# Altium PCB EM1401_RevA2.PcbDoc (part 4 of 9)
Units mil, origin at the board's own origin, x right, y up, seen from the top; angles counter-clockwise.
Board outline 7800 x 5300 mil, 6 copper layers (Top Layer, MidLayer1, MidLayer2, MidLayer3, MidLayer4, Bottom Layer), stack 16.8 mil thick; 751 components, 531 nets, 2554 pads, 1388 vias.
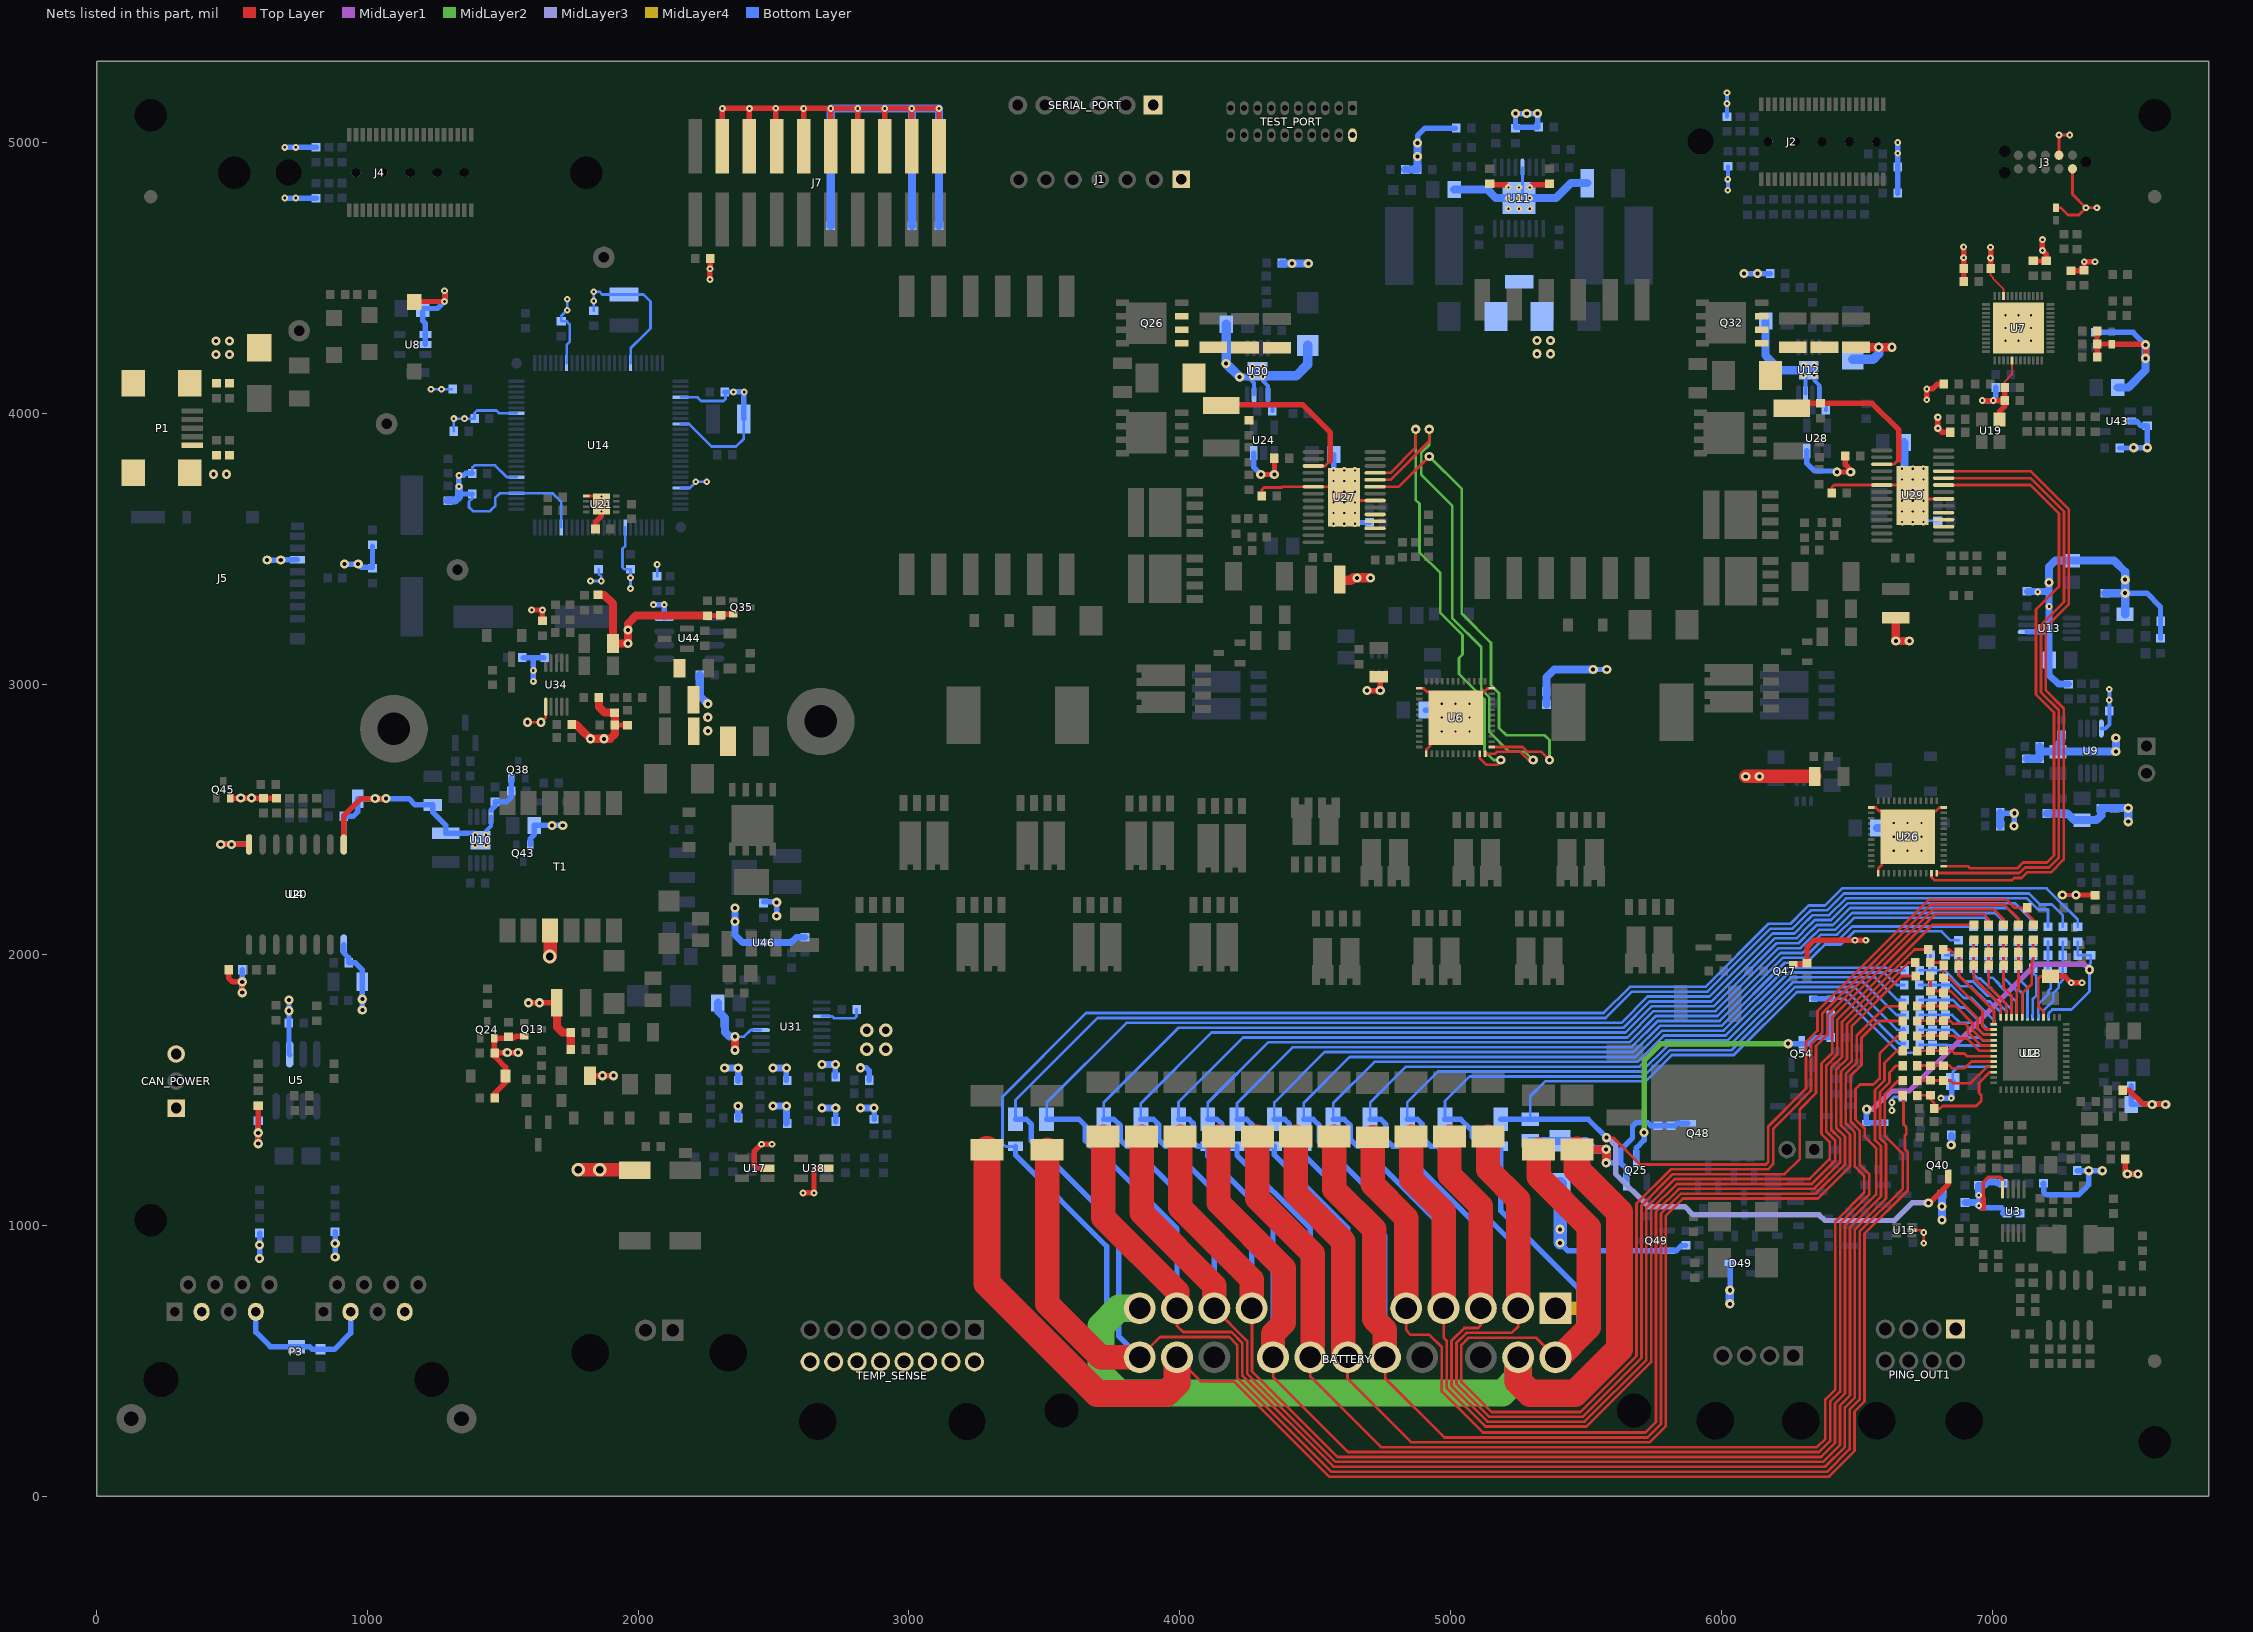
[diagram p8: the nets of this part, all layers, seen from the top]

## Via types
v1: diameter 25, hole 10, Top Layer to Bottom Layer, tented both sides, 275 vias
v2: diameter 16, hole 8, Top Layer to Bottom Layer, tented both sides, 240 vias
v3: diameter 34, hole 15, Top Layer to Bottom Layer, tented both sides, 158 vias
v4: diameter 34, hole 15, Top Layer to Bottom Layer, 154 vias
v5: diameter 34, hole 15, Top Layer to Bottom Layer, tented top, 95 vias
v6: diameter 34, hole 15, Top Layer to Bottom Layer, tented bottom, 89 vias
v7: diameter 25, hole 10, Top Layer to Bottom Layer, tented bottom, 75 vias
v8: diameter 25, hole 10, Top Layer to Bottom Layer, 62 vias
v9: diameter 28, hole 8, Top Layer to Bottom Layer, tented both sides, 60 vias
v10: diameter 24, hole 8, Top Layer to Bottom Layer, 53 vias
v11: diameter 25, hole 10, Top Layer to Bottom Layer, tented top, 28 vias
v12: diameter 50, hole 28, Top Layer to Bottom Layer, 28 vias
v13: diameter 25, hole 8, Top Layer to Bottom Layer, tented both sides, 18 vias
v14: diameter 50, hole 28, Top Layer to Bottom Layer, tented top, 12 vias
v15: diameter 25, hole 8, Top Layer to Bottom Layer, tented top, 9 vias
v16: diameter 20, hole 8, Top Layer to Bottom Layer, tented both sides, 9 vias
v17: diameter 24, hole 8, Top Layer to Bottom Layer, tented bottom, 4 vias
v18: diameter 24, hole 8, Top Layer to Bottom Layer, tented top, 4 vias
v19: diameter 28, hole 10, Top Layer to Bottom Layer, tented both sides, 3 vias
v20: diameter 35, hole 14, Top Layer to Bottom Layer, 3 vias
v21: diameter 50, hole 28, Top Layer to Bottom Layer, tented both sides, 2 vias
v22: diameter 50, hole 28, Top Layer to Bottom Layer, tented bottom, 2 vias
v23: diameter 30, hole 14, Top Layer to Bottom Layer, tented top, 2 vias
v24: diameter 28, hole 10, Top Layer to Bottom Layer, 1 vias
v25: diameter 35, hole 14, Top Layer to Bottom Layer, tented both sides, 1 vias
v26: diameter 35, hole 14, Top Layer to Bottom Layer, tented top, 1 vias

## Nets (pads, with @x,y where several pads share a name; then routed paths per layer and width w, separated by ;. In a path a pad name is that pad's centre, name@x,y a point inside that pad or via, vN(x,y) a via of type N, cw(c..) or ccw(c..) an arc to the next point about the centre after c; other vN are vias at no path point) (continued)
BAT0: BATTERY.1 BATTERY.19 C1.1 C6.2 C15.1 C17.1 C18.1 C19.1 C20.1 C21.2 C22.2 C24.2 C25.2 C27.2 C28.2 C29.2 C30.2 C31.2 C32.2 C33.1 C34.1 C35.2 C36.2 C37.2 C38.1 C39.1 C40.1 C41.2 C42.2 C43.1 C44.1 C45.2 C47.2 C48.1 C50.1 C52.2 C54.1 C56.1 C60.2 C65.1 C66.1 C67.2 C68.1 C69.2 C72.2 C73.1 C80.1 C82.1 C83.1 C84.1 C85.1 C86.1 C87.1 C88.1 C89.1 C92.2 C93.2 C94.1 C95.1 C98.2 C99.1 C101.1 C102.1 C103.1 C104.1 C105.2 C106.2 C107.1 C111.1 C112.1 C115.1 C117.1 C118.1 C119.1 C120.1 C122.2 C123.2 C124.2 C128.1 C130.2 C132.2 C133.2 C134.2 C138.1 C140.2 C141.2 C142.2 C143.2 C144.2 C145.2 C146.2 C147.2 C148.2 C149.2 C150.2 C151.2 C155.2 C156.2 C157.1 C160.2 C161.2 C162.2 C166.1 C167.2 C168.1 C196.2 C197.2 C200.1 C201.1 C202.1 C203.1 C204.1 C207.1 C208.1 C209.1 C210.1 C214.1 C215.2 C216.2 C220.2 C222.2 C224.1 C225.2 C226.2 C227.1 C229.1 C230.1 C231.1 C233.2 C235.1 C236.2 C239.2 C240.2 C241.1 C242.1 C243.1 C244.1 D1.2 D4.2 D6.2 D8.2 D9.2 D17.1 D20.1 D39.2 D42.1 D49.3 D51.2 D62.2 D63.2 F15.2 F19.1 J1.1 J2.39 J2.40 J2.41 J2.42 J2.43 J3.2 J3.10 J4.39 J4.40 J4.41 J4.42 J4.43 J5.6 J7.4 J7.6 J7.8 J7.10 J7.12 J7.14 J7.16 J7.18 J7.20 NT3.2 NT4.2 NT6.2 P1.5 P1.6 P1.7 P1.8 P1.9 PING_OUT1.1 Q13.2 Q24.2 Q26.1 Q26.2 Q26.3 Q32.1 Q32.2 Q32.3 Q35.2 Q38.2 Q43.2 Q45.2 Q47.2 Q49.2 R15.1 R22.2 R36.2 R39.2 R46.2 R57.2 R61.2 R77.1 R78.1 R79.1 R82.2 R90.1 R91.1 R94.1 R98.2 R113.2 R130.1 R146.1 R147.1 R149.1 R153.1 R169.2 R172.2 R179.1 R185.2 R187.1 R190.2 R197.1 R199.2 R211.2 R215.2 R216.2 R219.1 R222.1 R223.2 R224.1 R228.1 R241.2 R242.2 R244.2 R250.1 R251.2 R255.2 R256.2 R257.2 R279.2 R303.2 R304.2 SERIAL_PORT.1 SW1.1 T1.9 TEMP_SENSE.9 TEMP_SENSE.10 TEMP_SENSE.11 TEMP_SENSE.12 TEMP_SENSE.13 TEMP_SENSE.14 TEMP_SENSE.15 TEMP_SENSE.16 TEST_PORT.2 U2.4 U3.5 U4.9 U4.16 U6.1 U6.13 U6.36 U6.49 U7.5 U7.34 U7.49 U8.1 U8.2 U9.4 U10.4 U10.9 U11.5 U11.17 U12.1 U12.3 U12.9 U13.2 U14.4 U14.9 U14.21 U14.33 U14.45 U14.54 U14.57 U14.69 U14.82 U14.94 U15.2 U17.2 U18.4 U19.2 U20.9 U20.16 U21.5 U21.9 U24.3 U26.1 U26.13 U26.36 U26.49 U27.3 U27.4 U27.5 U27.7 U27.17 U27.20 U27.29 U28.3 U29.3 U29.4 U29.5 U29.7 U29.17 U29.20 U29.29 U30.1 U30.3 U30.9 U31.3 U31.12 U34.6 U38.2 U43.2 U44.4 U46.2 | length 43999.7
  Top Layer w7: C203.1@6994.44,4534 6994.44,4510.56 7003,4502 7003,4498 7041.88,4459.12 U7.34@7041.88,4434.09 ; C201.1@7046.44,4095 7046.44,4116.44 7073.38,4143.38 U7.5@7073.38,4195.91
  Top Layer w10: v3(1591,2859) v3(1641,2859) 1658.83,2876.83 U34.6@1658.83,2916.32 ; U21.5@1808.88,3694.53 1834.47,3694.53 U21.9@1864,3665 ; v11(2265,4534) v11@2265.56,4534.56 ; BATTERY.19@3990,513.9 4078.9,425 4200,425 4552,73 6397.73,73 6492.23,167.49 6492.23,313.35 6529.19,350.31 6529.19,970.45 6688.5,1129.77 6688.5,1272.02 6677.5,1283.02 6677.5,1333.07 6683,1338.57 6683,1364.35 6672.92,1374.44 6672.92,1477.09 R15.1@6669.35,1480.65 ; C128.1@4302.86,3695 4302.86,3717.44 4311.42,3726 4376.42,3726 4379.33,3728.92 U27.20@4493.28,3728.92 4569.07,3728.92 U27.29@4607.45,3690.53 4620.25,3677.74 U27.7@4721.62,3677.74 ; U27.17@4493.28,3805.69 4537.11,3805.69 4556.42,3825 ; U6.1@4885.06,2984.51 4900.49,2984.51 4914,2971 U6.49@4927.42,2971 ; U6.13@4910.65,2742.39 4910.65,2758.23 4924.42,2772 U6.49@4924.42,2801 ; U6.49@5110.42,2971 5123.42,2971 5136.93,2984.51 U6.36@5152.77,2984.51 ; C138.1@6408.86,3708 6408.86,3727.44 6416.42,3735 6592.64,3735 U29.20@6592.7,3735.06 6668.49,3735.06 6697.03,3706.52 U29.29@6706.88,3696.68 6719.67,3683.88 U29.7@6821.05,3683.88 ; U26.1@6554.06,2544.27 6570.15,2544.27 6583.42,2531 U26.49@6597.42,2531 ; U26.13@6579.65,2302.14 6579.65,2319.23 6592.42,2332 U26.49@6592.42,2348 ; U29.17@6592.7,3811.84 6638.25,3811.84 6655.42,3829 ; U15.2@6703.5,983 6740,983 v1(6748,975) v1(6748,935) ; U26.49@6778.42,2526 6782.42,2530 6791.42,2530 6805.68,2544.27 U26.36@6821.77,2544.27 ; U2.4@7189.91,1769.78 7189.91,1790.51 7170.42,1810 7170.42,1890.54 7170.47,1890.6 7170.47,1912.06 7179.07,1920.65 C1.1@7215.41,1920.65 C1.1@7233.41,1920.65 ; R90.1@7236,4759.62 7253.38,4759.62 7281,4732 7320,4732 v1(7347,4759) ; J3.2@7247,4953 v1(7247,5028) v1(7287,5028) ; J3.10@7297,4903 7297,4809 v1(7347,4759) ; v1(7387,4759) v1(7347,4759)
  Top Layer w12: 6967.42,1102 6967.42,1160.42 6987,1180 7029,1180 7038.84,1170.16 U3.5@7038.84,1133.84
  Top Layer w15: v3(7259.42,2221) v3(7309.42,2221) v3@7316.42,2221
  Top Layer w20: v4(458.44,2408.04) v4(498.44,2408.04) U20.16@563,2408.04 ; Q45.2@493,2579 v5(532.44,2579) v5(572.44,2579) R223.2@617,2579 ; R223.2@617,2579.12 C107.1@665,2579.12 ; U20.9@913,2408.04 913,2514 976,2577 v4(1028.86,2577) v4(1068.86,2577) ; SW1.1@1173,4410.95 1175.05,4413 v8(1285,4413) v8(1285,4453) ; C106.2@1470.56,1472 1470.56,1489.56 1510.47,1529.47 D51.2@1510.47,1553 1510.47,1584.53 1470.56,1624.44 R215.2@1470.56,1638 1468.59,1639.97 Q24.2@1468.59,1692.01 1520.01,1692.01 1521,1693 1542,1693 1549,1700 1579.42,1700 Q13.2@1580.01,1699.41 ; R215.2@1470.56,1639 v5(1516.82,1639) v5(1556.82,1639) ; v3(1595.14,1823) v3(1635.14,1823) C162.2@1699.7,1823 ; v1(1606.5,3273.5) v1(1646.5,3273.5) C160.2@1646.5,3233.56 ; C102.1@1822.3,1554 v5(1868.56,1554) v5(1908.56,1554) ; C115.1@1842.44,3575 1842.44,3599.44 1864,3621 v17(1864,3637.44) U21.9@1864,3665 ; C168.1@1914.18,2848.88 C168.1@1914.06,2849 1959.88,2849 R219.1@1960,2848.88 ; C104.1@2256,3252.88 2256.56,3253.44 R244.2@2305,3253.44 2308.97,3257.41 Q35.2@2350.5,3257.41 ; v11(2265,4494) v11(2265,4534) ; v11@2265.56,4534.56 C33.1@2265.56,4572 ; J7.4@2311,4986 v8(2311,5126) v8(2411,5126) ; J7.6@2411,4986 v8(2411,5126) ; U17.2@2477.66,1212 2439.42,1212 2429.42,1222 2429.42,1275 v1(2455.42,1301) v1(2494.42,1301) ; J7.8@2508,4987 v8(2508,5127) ; v11(2609,1121) v11(2649,1121) 2649.42,1121.42 2649.42,1202 2659.42,1212 U38.2@2695.42,1212 ; J7.10@2611,4986 v8(2611,5126) ; J7.12@2711,4986 v8(2711,5126) ; J7.14@2811,4986 2811,5122 2807,5126 v8(2711,5126) ; v8(2811,5126) v8@2907,5126 ; J7.16@2911,4986 v8(2911,5126) 3006,5126 3010,5122 J7.18@3010,4986 ; v8(3010,5126) v8(3111,5126) J7.20@3111,4986 ; R179.1@4156.42,4031.74 4453.68,4031.74 4556.42,3929 4556.42,3825 ; v5(4299.42,3774) v5(4349.42,3774) 4349.86,3774.44 C230.1@4349.86,3834 ; v5(4691.42,2976) v5@4735.42,2976 ; v5(4740.42,2976) v5@4735.42,2976 ; C207.1@4740.42,3026.7 4740.42,2981 v5@4735.42,2976 ; C95.1@5145,4844.5 5203.5,4844.5 v10(5213.63,4834.37) ; v10(5292.37,4834.37) 5301.5,4843.5 C94.1@5366,4843.5 ; Q47.2@6265.91,1965.59 6312.89,1965.59 R169.2@6316.42,1969.12 6316.42,2027.42 6343,2054 v1(6494,2054) v1(6534,2054) ; R197.1@6266.42,4036.74 C235.1@6366.42,4036.74 6557.26,4036.74 6655.42,3938.58 6655.42,3829 ; v5(6427.84,3783.15) v5(6477.84,3783.15) ; C231.1@6457.86,3842 6457.86,3810.13 v5@6477.84,3790.15 ; v1(6759,4050) v11(6759,4090) 6780,4090 6798,4108 R82.2@6818.01,4108 ; v19(6800,3985) v19(6800,3945) 6815,3930 C101.1@6845.88,3930 ; v3@6814,1021 v3(6815.42,1021) ; v1@6894.32,4574.56 v1@6894.88,4574 ; C242.1@6894.88,4487 C241.1@6894.88,4535 v1@6894.88,4574 ; v1(6894.88,4614.56) v1(6894.88,4574.56) v1@6894.88,4574 ; v1(6964,4047) v1(7004,4047) C40.1@7046.88,4047 ; 6967.42,1064 6967.42,1102 ; v1@6993.88,4573.56 6994.44,4573 C203.1@6994.44,4534 ; v1(6994.44,4573.56) v1(6994.44,4613.56) ; U19.2@7027.5,3977.5 7027.5,4007.5 7046.88,4026.88 C40.1@7046.88,4047 ; C201.1@7046.44,4095 7046.44,4047.44 C40.1@7046.88,4047 ; C214.1@7152,4563.12 7152.56,4562.56 C204.1@7200,4562.56 7200,4587.47 v1(7186,4601.47) v1(7186,4641.47) ; C1.1@7233.41,1920.65 7268.35,1920.65 v1(7292,1897) v1(7332,1897) ; C224.1@7292,4527.12 7339.56,4527.12 C227.1@7340,4527.56 v1(7340,4560) v1(7380,4560) ; v3@7316.42,2221 R303.2@7380,2221 ; C202.1@7387.56,4304 7387.56,4256.56 C244.1@7388.12,4256 ; C243.1@7388.12,4208 C244.1@7388.12,4256 ; R57.2@7482.53,1500 7506.42,1500 7558.64,1447.77 v3(7591.2,1447.77) v3(7641.2,1447.77) v3@7642.2,1447.77 ; R279.2@7491.53,1246 7491.53,1198.8 v3(7499.34,1191) v3(7539.34,1191) ; v3(7567,4203) v3(7567,4253) 7565.24,4254.76 R91.1@7442,4254.76 7440.76,4256 C244.1@7388.12,4256 ; v8(2411,5126) 2507,5126 v8(2508,5127) ; v8(2508,5127) 2610,5127 v8(2611,5126) ; v8(2611,5126) v8(2711,5126)
  Top Layer w30: C162.2@1699.7,1823 1699.7,1734.3 1721,1713 C82.1@1750.88,1713 1750.88,1651.12 C83.1@1751,1651 ; C167.2@1754.06,2851 1771.07,2851 1792.81,2829.26 1792.81,2828.69 v4(1823.5,2798) v4(1873.5,2798) 1897,2798 1914.06,2815.06 C168.1@1914.06,2849 1914.06,2893.32 C166.1@1912.5,2894.88 1876.12,2894.88 1855,2916 R222.1@1855,2950 ; R228.1@1851.5,3329.56 1874.44,3329.56 1907.06,3296.94 1907.06,3212.56 1907.15,3212.47 C157.1@1907.15,3150 ; C157.1@1907.15,3148 C157.1@1907.15,3150 ; C104.1@2256,3252.88 1991.88,3252.88 1962,3223 v3(1962,3200) v3(1962,3150) C157.1@1907.15,3150 ; v5(2357.3,1648) v5(2357.3,1698) ; C134.2@6497.75,4244.01 v3(6581.42,4244) v5(6630,4244) v5@6631.42,4244 ; C216.2@6644.42,3244.85 6644.42,3159 v4(6644.57,3158.85) 6644.72,3159 v4(6694.42,3159)
  Top Layer w35: C215.2@4602.07,3383 4632.42,3383 4641.42,3392 v5(4654.42,3392) v5(4704.42,3392)
  Top Layer w50: v12(1674,1994) 1674.63,1994.63 T1.9@1674.63,2090.76 ; v12(1778,1206) v12(1858,1206) F19.1@1987,1206 ; v3(6090.42,2659) v3(6140.42,2659) C209.1@6345.27,2659
  Top Layer w100: F15.2@3287.96,1280.23 F15.2@3288.19,1280 3288.19,786.81 3695,380 3950,380 3990,420 BATTERY.19@3990,513.9
  MidLayer4 w50: BATTERY.1@5387.64,695 NT4.2@5500,695
  Bottom Layer w10: v7(1234.7,4089) v7(1273.7,4089) R61.2@1311.01,4089 ; C22.2@1318.73,3933.69 1318.73,3979.73 v7(1319.43,3980.43) v7(1358.43,3980.43) C44.1@1395.73,3980.43 1395.73,4000.73 1405.16,4010.16 1476.84,4010.16 1486.89,4000.11 U14.69@1550.85,4000.11 ; v7@1337.44,3770.56 v7(1338,3770) ; C43.1@1386.88,3773 C43.1@1386.88,3778 1386.88,3798.88 1396,3808 1471,3808 1515.11,3763.89 U14.57@1550.85,3763.89 ; C29.2@1387.44,3702 1387.44,3686.44 1375,3674 1375,3653 1389.5,3638.5 1452.56,3638.5 1472,3657.94 1472,3687 1489.83,3704.83 U14.54@1550.85,3704.83 1683.17,3704.83 1716.2,3671.8 U14.45@1716.2,3578.85 ; U14.82@1735.89,4185.15 1735.89,4252.89 1747,4264 1747,4328 1734.88,4340.12 C31.2@1716,4340.12 1716,4359 v1(1738,4381) v1(1738,4421) ; v1(1824,3381) v1(1864,3381) 1864,3397 1854,3407 C45.2@1854,3423.73 ; C48.1@1836,4379.12 v1(1836,4415) v1(1836,4449.09) 1856.91,4449.09 1866.91,4439.09 C41.2@1948,4439.09 2018.91,4439.09 2045.5,4412.5 2045.5,4313.5 2024.5,4292.5 2024.44,4292.5 1972.11,4240.17 U14.94@1972.11,4185.15 ; U14.33@1952.43,3578.85 1952.43,3510.14 1942.27,3499.98 1942.27,3430.73 1949.27,3423.73 C36.2@1972,3423.73 v1(1972,3393) v1(1972,3353) ; R36.2@2070,3399.12 v1(2070,3442) ; U14.21@2157.15,3724.52 2190.52,3724.52 v1(2213,3747) v1(2253,3747) ; U14.9@2157.15,3960.74 2188.26,3960.74 2271.5,3877.5 2361.5,3877.5 2390.17,3906.17 C47.2@2390.17,3979 ; U14.4@2157.15,4059.17 2218.83,4059.17 2232.85,4045.15 2315.15,4045.15 2322.27,4052.27 C30.2@2322.27,4078.85 ; v7@2351.85,4078.85 v7(2352,4079) ; v5@2364.3,1705 v5(2357.3,1698) 2391.5,1698 2415.71,1722.21 U31.12@2453.71,1722.21 ; U31.3@2678.12,1773.39 2716.27,1773.39 2723.33,1766.32 2799.74,1766.32 2806.53,1773.12 C149.2@2806.53,1799 ; D39.2@3393.42,1292.61 3356.81,1292.61 3345.42,1304 3345.42,1476 3654.42,1785 5565.62,1785 5662.62,1882 5941.62,1882 6174.62,2115 6255,2115 6304,2164 6304.29,2164 6322.79,2182.5 6382.79,2182.5 6446.17,2245.88 7201.73,2245.88 7316.41,2131.2 R130.1@7316.41,2103.77 ; v1(6630,1425) v1(6630,1455) 6630,1468 6637,1475 C69.2@6670.88,1475 ; 6724.25,3598.25 6728.88,3602.88 C197.2@6799.42,3602.88 ; C68.1@6854.42,1533 6854.42,1566.63 6874.49,1586.71 U18.4@7006.84,1586.71
  Bottom Layer w12: v10(5253,4795) 5265.8,4807.8 U11.5@5265.8,4908.19
  Bottom Layer w15: U10.9@1418,2427 1438,2447 1438,2457 1456.39,2475.39 U10.4@1456.39,2509.63 U10.4@1456.39,2510.66 ; U30.3@4274.62,4069.37 4274.62,4112.43 4267.73,4119.31 v10(4267.73,4135.31) U30.9@4287.42,4155 4307.42,4135 4307.42,4119 4325.8,4100.61 U30.1@4325.8,4069.37 4325.8,4040.61 4341.98,4024.44 C225.2@4341.98,4009 ; C112.1@6021,5096 v1(6021,5144) v1(6021,5184) ; v1(6024,4823.88) v1(6024,4863.88) C111.1@6024,4911.88 ; U12.3@6310.62,4073.37 6310.62,4146.2 U12.9@6323.42,4159 6343.42,4139 6343.42,4121 6361.8,4102.61 U12.1@6361.8,4073.37 6361.8,4045.61 6386.42,4021 C226.2@6386.42,4012 ; U9.4@7403.59,2836 7418,2836 7433.12,2851.12 C161.2@7433.12,2900 7433.12,2940.88 v7(7433,2941) 7433,2980.76 v7(7433.12,2980.88)
  Bottom Layer w20: v4(458.44,2408.04) v4(498.44,2408.04) U4.9@563,2408.04 ; v6(630,3458) v6(680,3458) 680.55,3458.55 J5.6@741.56,3458.55 ; v1(695.12,4794.88) v1(735.12,4794.88) C103.1@811,4794.88 ; v1(695.12,4982.12) v1(735.12,4982.12) C50.1@811,4982.12 ; U4.16@913,2408.04 913.12,2408.16 C80.1@913.12,2512 948,2512 964.3,2528.3 C15.1@964.3,2577 v4(1028.86,2577) v4(1068.86,2577) 1153,2577 1176.3,2553.7 C60.2@1242,2553.7 1242,2526 1289,2479 C67.2@1289,2449.3 1395.7,2449.3 U10.9@1418,2427 ; v4(916,3443) v4(966,3443) 978.01,3430.99 1019,3430.99 C25.2@1019,3510.01 ; U8.2@1214.24,4254 U8.1@1214.24,4291.4 1214.24,4331.76 1205,4341 C32.2@1205,4387 1259,4387 v8(1285,4413) v8(1285,4453) ; v7@1337.44,3770.56 1355.56,3770.56 1363,3778 C43.1@1386.88,3778 ; 1338,3696 1344,3702 C29.2@1387.44,3702 ; v7(1338,3730) v7(1338,3770) ; U10.4@1456.43,2534.43 1472,2550 R216.2@1472,2564.88 1513.88,2564.88 1532,2583 R250.1@1532,2605.5 1532,2651.42 Q38.2@1531.41,2652.01 ; C28.2@1576,3098 1613,3098 ; Q43.2@1601.59,2406.5 1601.59,2429.59 1617,2445 C65.1@1617,2478 v3(1681.56,2478) v3(1721.56,2478) ; v7(1613,3010) v7(1613,3050) 1613,3098 ; C27.2@1651.01,3098 1613,3098 ; v1(2056.48,3293.52) v1(2096.48,3293.52) U44.4@2096.48,3244 ; C30.2@2319.12,4078.85 2322.27,4078.85 v7@2351.85,4078.85 ; v7(2352,4079) v7(2392,4079) 2390.17,4077.17 C47.2@2390.17,3979 ; C239.2@2462.97,2196 2463.42,2195.56 2509.86,2195.56 v5(2511.42,2194) v5(2511.42,2144) ; C148.2@2547.42,1536 v6(2547.42,1582) ; v6(2728.42,1595.12) 2728.53,1595 C146.2@2728.53,1549 ; v3@2729.42,1441.12 v3@2729.53,1441 ; C143.2@2729.53,1384 v3@2729.53,1434.88 ; v6(2821.42,1583) 2842.42,1583 2853.53,1571.88 C142.2@2853.53,1537 ; C141.2@2871.42,1392.12 v3(2871.42,1435) ; D39.2@3393.42,1292.61 3393.42,1260.58 3730,924 3730,465 3795,400 3953,400 3990,437 BATTERY.19@3990,513.9 ; U24.3@4273.42,3853.51 4273.42,3800 v5(4299.42,3774) ; v10(4568.08,3788.96) 4568.42,3789.29 C220.2@4568.42,3848 ; v10(4646.82,3592.11) 4651.6,3596.88 C196.2@4701.42,3596.88 ; v6(4878.6,4998.6) 4878.6,5025.6 4906,5053 R153.1@5018.01,5053 ; C208.1@4905.92,2904 4995.49,2904 v13(5018.92,2927.43) ; v13(5070.1,2927.43) 5070.67,2928 C17.1@5102.36,2928 ; v4(5404.42,936.42) 5433.64,907.2 Q49.2@5799,907.2 5833.2,907.2 5852.88,926.88 R185.2@5869.56,926.88 ; v5(5527,3054) v5(5577,3054) ; v6@6032.4,762.4 D49.3@6032.4,862 ; v3(6083.42,4516) v3(6133.42,4516) R190.2@6180.3,4516 ; U28.3@6316.01,3861 6316.01,3815.4 6344.42,3787 6424.69,3787 v5@6427.84,3790.15 ; R39.2@6651.88,4813 R22.2@6651.88,4909 6652,4909.12 v1(6652,4960) 6652,4999.88 v1(6651.88,5000) ; v13(6739.1,2487.18) 6739.28,2487 C118.1@6772.86,2487 ; v1(6811.42,1471) v1(6849,1471) 6851.42,1471 6851.42,1530 C68.1@6854.42,1533 ; v1@6949.68,1111.56 v1@6951.12,1113 ; v1(6951.12,1112) v1@6951.12,1075.12 ; v1@6952,1076 v1@6951.12,1075.12 ; v1(6964,4047) v1(7004,4047) 7013.44,4056.44 R146.1@7013.44,4096 ; C119.1@7029.41,2524.98 7031.39,2523 v6(7082,2523) 7082,2477 v6(7081,2476) ; C6.2@7038.88,1046.12 C6.2@7055,1046.12 ; C236.2@7103,1046.12 C6.2@7055,1046.12 ; U13.2@7129.98,3192.97 7210.04,3192.97 ; R256.2@7187.42,1153.88 R256.2@7190.42,1156.88 7190.42,1124.58 7201,1114 7320,1114 7357,1151 v3(7357,1203) ; R257.2@7314.53,1203 v3(7357,1203) ; R149.1@7382,4299 7521,4299 v3(7567,4253) ; v3(7407,1203) v3(7357,1203) ; C39.1@7471.12,3872 7522,3872 v3(7523,3873) v3(7573,3873) C99.1@7573,3953.44 7550.31,3953.44 7532.75,3971 U43.2@7510.24,3971 ; v6(7491.64,3335.68) 7571.32,3335.68 7622.12,3284.88 7622.12,3232.12 7622,3232 C85.1@7622,3169.12 ; v3(7499.34,1191) v3(7539.34,1191) ; C72.2@7513.41,1447.65 C72.2@7513.53,1447.77 ; C73.1@7513.53,1516.65 C73.1@7513.53,1515.65 C72.2@7513.53,1447.77 ; v3(7641.2,1447.77) v3(7591.2,1447.77) C72.2@7513.53,1447.77 ; v1(6951.12,1074) v1@6951.12,1075.12 ; v1(6951.12,1074) 6950.56,1074.56 v1@6951.12,1075.12 ; v1(6951.12,1074) 6959.12,1066 7035.12,1066 C6.2@7055,1046.12 ; C38.1@5240,5056.99 5321.5,5056.99 v3(5321.5,5107) v3(5281.5,5107) v3(5240,5106.99) C38.1@5240,5056.99
  Bottom Layer w25: v3(2319.42,1582) v3(2369.42,1582) 2369.42,1536.12 C151.2@2369.53,1536 ; v5(2357.42,2173) v5(2357.42,2123) 2357.42,2074 2386.01,2045.4 U46.2@2415.93,2045.4 2564.82,2045.4 2584.42,2065 C240.2@2616.42,2065 ; C150.2@2369.42,1398 v6(2369.42,1442) ; v3(2497.42,1442) v3(2547.42,1442) 2547.42,1378.12 C147.2@2547.53,1378 ; v6(2497.42,1582) v6(2547.42,1582) ; v6(2678.42,1595.12) v6(2728.42,1595.12) ; v3(2679.42,1435) v3(2729.42,1435) ; v3(2821.42,1435) v3(2871.42,1435) ; v3(4221.42,4134) 4266.42,4134 v10(4267.73,4135.31) ; v3(6849,1298) 6849.88,1297.12 R46.2@6849.88,1335 ; R304.2@6900,1085.56 6939.56,1085.56 v1@6950.56,1074.56 ; v1@6949.68,1111.56 6949.42,1111.82 R199.2@6949.42,1149 6972,1149 6984,1161 7015,1161 7019.12,1156.88 R255.2@7040.42,1156.88 ; R94.1@7129.64,3342.12 7205.08,3342.12 7210.64,3336.57 ; 7210.04,3192.97 7210.64,3193.57 ; v6@7210.64,3391 v6(7210.64,3375.57) 7210.64,3336.57 ; C117.1@7282,3000.12 7244.88,3000.12 7210.64,3034.36 C52.2@7210.64,3088.57 7210.64,3193.57 ; 7210.64,3193.57 v7(7210.64,3286.57) 7210.64,3336.57
  Bottom Layer w30: R147.1@1297,3677.44 1324.44,3677.44 1338,3691 1338,3696 v7(1338,3730) ; C229.1@2227.44,3034 2227.44,2956.98 v25(2257.42,2927) ; C145.2@2295.42,1823 2295.42,1792 2320.3,1767.12 C144.2@2320.3,1748 2320.3,1715.12 2337.42,1698 v5(2357.3,1698) v5(2357.3,1648) ; R77.1@2711,4692.12 v8(2711,5126) v8(2811,5126) v8(2911,5126) v8(3010,5126) ; R78.1@3011,4692.12 3011,5125 v8(3010,5126) ; R79.1@3111,4692.12 v8(3111,5126) v8(3010,5126) ; R172.2@4376.53,4553.44 v6(4414.98,4553.44) v4(4474.98,4553.44) ; C89.1@4832.91,4901 C88.1@4877.88,4901 v6@4877.88,4947.88 ; v6@4878,4948 v6(4878.6,4948.6) v6(4878.6,4998.6) ; C92.2@5014,4826 5136,4826 5167,4795 v10(5213.63,4795) v10(5253,4795) v10(5292.37,4795) 5390,4795 5445,4850 C93.2@5504.91,4850 ; C19.1@5354.53,2924 5354.53,2971.88 C18.1@5354.42,2972 5354.42,3025.42 5383,3054 v5@5517,3054 ; v3(5369.4,4219.6) v3@5370,4219 ; v3(5369.4,4268.6) v3@5370,4268 ; v6(6031.4,711.4) v6(6031.4,761.4) v6@6032,762 ; C140.2@6163.42,4341 6163.42,4213.24 6204.42,4172.24 6204.42,4169 6214.42,4159 U12.9@6323.42,4159 ; C210.1@6574.85,2467.98 6644.98,2467.98 ; v10(6667.51,3755.73) 6676.42,3764.64 6676.42,3892 C222.2@6675.42,3893 ; v3(6815.42,1021) v3(6815.42,1071) R113.2@6815.42,1116 ; C120.1@7029.41,2476.98 C119.1@7029.41,2524.98 ; C86.1@7127,2724.12 R251.2@7175,2724.12 ; R251.2@7175,2726.12 7176.12,2727.24 7176.12,2748 ; C87.1@7176.12,2770 7176.12,2748 ; C20.1@7201.12,2522 7201.24,2521.88 C34.1@7260,2521.88 7279.12,2521.88 7303,2498 C37.2@7332,2498 7386,2498 7403,2515 R242.2@7403,2541.88 R241.2@7453,2541.88 v6(7503,2541.88) v6(7503,2491.88) ; v6@7210.64,3391 7210.64,3433.22 7233.42,3456 C56.1@7293.42,3456 7450.42,3456 7491.64,3414.78 v6(7491.64,3385.68) v6(7491.64,3335.68) ; C105.2@7257,2812.44 7257,2790 7241,2774 C35.2@7243,2751 ; R98.2@7416.64,3335.68 v6(7491.64,3335.68) ; v6(7457,2801) v6(7457,2751) C35.2@7243,2751 ; C98.2@7464,4096 7504,4096 7567,4159 v3(7567,4203) v3(7567,4253) ; C54.1@7491.64,3257.57 v6(7491.64,3335.68) ; 7176.12,2748 7179.12,2751 C35.2@7243,2751
  Bottom Layer w35: C130.2@4171.42,4329 v5(4171.42,4184) v3(4221.42,4134) ; U30.9@4287.42,4155 4295.42,4155 4312.42,4138 4430.42,4138 4472.42,4180 D17.1@4472.42,4250.52 ; D20.1@6485.42,4200.26 6561.68,4200.26 6581.42,4220 v3(6581.42,4244)
  Bottom Layer w50: v4(5404.42,936.42) v4(5404.42,986.42) D42.1@5404.42,1155.52
  other v3: 5319.4,4219.6 5319.4,4268.6
  other v4: 432,3775 480,3775 441,4217 491,4217 441,4267 491,4267
  other v7: 7168.64,3340.57
  other v10: 1398.32,2404.32 1437.69,2404.32 1398.32,2443.68 1437.69,2443.68 4568.08,3592.11 4607.45,3592.11 6667.51,3598.25 6706.88,3598.25 6746.25,3598.25 4568.08,3631.48 4607.45,3631.48 4646.82,3631.48 6667.51,3637.62 6706.88,3637.62 6746.25,3637.62 4568.08,3670.85 4607.45,3670.85 4646.82,3670.85 6667.51,3676.99 6706.88,3676.99 6746.25,3676.99 4568.08,3710.22 4607.45,3710.22 4646.82,3710.22 6667.51,3716.36 6706.88,3716.36 6746.25,3716.36 4568.08,3749.59 4607.45,3749.59 4646.82,3749.59 6706.88,3755.73 6746.25,3755.73 4607.45,3788.96 4646.82,3788.96 6667.51,3795.1 6706.88,3795.1 6746.25,3795.1 4307.1,4135.31 4267.73,4174.69 4307.1,4174.69 5213.63,4755.63 5253,4755.63 5292.37,4755.63 5253,4834.37
  other v12: 2844.42,1652 2914.42,1652 2844.42,1722 2914.42,1722
  other v13: 6636.73,2384.82 6687.92,2384.82 6739.1,2384.82 6636.73,2436 6687.92,2436 6739.1,2436 6636.73,2487.18 6687.92,2487.18 4967.73,2825.06 5018.92,2825.06 5070.1,2825.06 4967.73,2876.24 5018.92,2876.24 5070.1,2876.24 4967.73,2927.43
  other v16: 7049.76,4267.76 7097,4267.76 7144.24,4267.76 7049.76,4315 7097,4315 7144.24,4315 7049.76,4362.24 7097,4362.24 7144.24,4362.24
  other v17: 1844.32,3665 1883.68,3665 1864,3692.56
  other v18: 6303.73,4139.31 6343.1,4139.31 6303.73,4178.69 6343.1,4178.69
  other v20: 2257.42,2827
  other v26: 2257.42,2877
BAT1: BATTERY.20 D35.2 D39.1 F14.2 R14.1 R124.1 | length 10906.7
  Top Layer w10: BATTERY.20@3852.2,513.9 3927.31,589 4183,589 4212,560 4212,439.22 4560.22,91 6390.28,91 6474.23,174.95 6474.23,320.8 6511.19,357.76 6511.19,977.91 6670.5,1137.22 6670.5,1263.87 6604,1330.37 6604,1486.21 6653.45,1535.65 R14.1@6669.35,1535.65
  Top Layer w90: F14.2@3510.19,1280 3510.19,711.81 3708.1,513.9 BATTERY.20@3852.2,513.9
  Bottom Layer w10: D39.1@3393.42,1393 3393.42,1464 3696.42,1767 5573.07,1767 5670.07,1864 5949.07,1864 6182.07,2097 6262.46,2097 6311.46,2146 6311.75,2146 6330.25,2164.5 6390.25,2164.5 6452.75,2227 7135.76,2227 7176.88,2185.88 7220.54,2185.88 7261.41,2145 R124.1@7261.41,2103.77
  Bottom Layer w20: D39.1@3393.42,1393 3433.42,1393 3451.42,1375 3451.42,1314 3472.81,1292.61 D35.2@3508.42,1292.61 3508.42,1258.58 3775.15,991.85 3775.15,590.95 BATTERY.20@3852.2,513.9
BAT2: BATTERY.8 D32.2 D35.1 F13.2 R13.1 R123.1 | length 10269.1
  Top Layer w10: BATTERY.8@3990,695 3990,630 4013,607 4190.46,607 4231,566.46 4231,447.09 4568.09,110 6383.82,110 6456.23,182.41 6456.23,328.26 6493.19,365.22 6493.19,985.37 6608,1100.18 6608,1300.91 6586,1322.91 6586,1493.66 6621,1528.66 6621,1566 6645.65,1590.65 R13.1@6669.35,1590.65
  Top Layer w90: F13.2@3717.42,1329 3717.42,1029.58 3990.29,756.71 BATTERY.8@3990.29,695
  Bottom Layer w10: D35.1@3508.42,1393 3508.42,1454 3803.42,1749 5631.06,1749 5728.06,1846 5956.53,1846 6189.53,2079 6269.91,2079 6318.91,2128 6319.2,2128 6337.7,2146.5 6397.7,2146.5 6460.2,2209 7128.3,2209 7169.42,2167.88 7205.62,2167.88 7206.41,2167.09 R123.1@7206.41,2103.77
  Bottom Layer w20: D35.1@3508.42,1393 3627.42,1393 3651.42,1369 3651.42,1314 3672.81,1292.61 D32.2@3719.42,1292.61 3719.42,1259.58 3990,989 BATTERY.8@3990,695
BAT3: BATTERY.7 D29.2 D32.1 F12.2 R12.1 R122.1 | length 9736
  Top Layer w10: BATTERY.7@4127.8,695 4127.91,695 4249,573.91 4249,454.54 4575.54,128 6376.37,128 6438.23,189.86 6438.23,335.72 6475.19,372.68 6475.19,992.82 6590,1107.63 6590,1293.46 6567.66,1315.8 6567.66,1500.77 6603,1536.12 6603,1601 6647.65,1645.65 R12.1@6669.35,1645.65
  Top Layer w90: F12.2@3859.42,1329 3859.42,1047.58 4128.09,778.91 BATTERY.7@4128.09,695
  Bottom Layer w10: D32.1@3719.42,1393 3719.42,1455 3995.42,1731 5638.52,1731 5735.52,1828 5963.99,1828 6196.99,2061 6277.37,2061 6326.37,2110 6326.66,2110 6345.16,2128.5 6405.16,2128.5 6467.66,2191 7084.42,2191 7084.42,2190.41 7084.71,2190.71 7151.41,2124 R122.1@7151.41,2103.77
  Bottom Layer w20: D32.1@3719.42,1393 3757.42,1393 3780.42,1370 3780.42,1317 3804.81,1292.61 D29.2@3856.42,1292.61 3856.42,1258.58 4127.8,987.2 BATTERY.7@4127.8,695
BAT4: BATTERY.6 D29.1 D43.2 F11.2 R11.1 R120.1 | length 9556.5
  Top Layer w10: BATTERY.6@4267,695 4267,462 4583,146 6368.91,146 6420.23,197.32 6420.23,343.17 6457.19,380.13 6457.19,1000.28 6572,1115.09 6572,1286 6530,1328 6530,1358 6496,1392 6496,1504 6513,1521 6562.43,1521 6585,1543.57 6585,1635 6650.65,1700.65 R11.1@6669.35,1700.65
  Top Layer w90: F11.2@4001.42,1329 4001.42,1065.58 4265.88,801.12 BATTERY.6@4265.88,695
  Bottom Layer w10: D29.1@3856.42,1393 3856.42,1452 4117.42,1713 5645.97,1713 5742.97,1810 5971.44,1810 6204.44,2043 6284.82,2043 6333.82,2092 6334.11,2092 6352.61,2110.5 6412.61,2110.5 6475.11,2173 7055.42,2173 7096.41,2132 R120.1@7096.41,2103.77
  Bottom Layer w20: D29.1@3856.42,1393 3902.42,1393 3922.42,1373 3922.42,1318 3947.81,1292.61 D43.2@3995.42,1292.61 3995.42,1258.58 4265.59,988.41 BATTERY.6@4265.59,695
BAT5: BATTERY.17 D40.2 D43.1 F10.2 R10.1 R118.1 | length 9458.5
  Top Layer w10: BATTERY.17@4345,509 4345,441 4622,164 6361.46,164 6402.23,204.77 6402.23,350.63 6439.19,387.59 6439.19,1007.73 6546,1114.54 6546,1191 6511,1226 6511,1351 6478,1384 6478,1553.84 6518,1593.84 6518,1694 6579.65,1755.65 R10.1@6669.35,1755.65
  Top Layer w90: F10.2@4143.42,1329 4143.42,1083.58 4384.42,842.58 4384.42,641.42 4344.33,601.33 BATTERY.17@4344.33,513.9
  Bottom Layer w10: D43.1@3995.42,1393 3995.42,1456 4234.42,1695 5653.43,1695 5750.43,1792 5978.9,1792 6211.9,2025 6292.28,2025 6341.28,2074 6341.57,2074 6360.07,2092.5 6420.07,2092.5 6482.57,2155 7010.42,2155 7040.41,2125 R118.1@7040.41,2103.77
  Bottom Layer w20: D43.1@3995.42,1393 4034.42,1393 4049.42,1378 4049.42,1309 4065.81,1292.61 D40.2@4103.42,1292.61 4103.42,1256.58 4344.33,1015.67 BATTERY.17@4344.33,513.9
BAT6: BATTERY.16 D37.2 D40.1 F9.2 R9.1 R116.1 | length 9134.5
  Top Layer w10: BATTERY.16@4482.13,513.9 4482.13,442.87 4743,182 6354,182 6384.23,212.23 6384.23,358.08 6421.19,395.04 6421.19,1015.19 6528,1122 6528,1183.54 6493,1218.54 6493,1343.54 6460,1376.54 6460,1561.29 6500,1601.29 6500,1701.46 6609.2,1810.65 R9.1@6669.35,1810.65
  Top Layer w90: F9.2@4286.42,1329 4286.42,1100.58 4491,896 4491,522.48 BATTERY.16@4482.42,513.9
  Bottom Layer w10: D40.1@4103.42,1393 4103.42,1454 4326.42,1677 5660.89,1677 5757.89,1774 5986.35,1774 6219.35,2007 6299.73,2007 6348.73,2056 6349.03,2056 6367.53,2074.5 6427.53,2074.5 6490.03,2137 6973.42,2137 6986.41,2124 R116.1@6986.41,2103.77
  Bottom Layer w20: D40.1@4103.42,1393 4137.42,1393 4155.42,1375 4155.42,1313 4175.81,1292.61 D37.2@4211.42,1292.61 4211.42,1259.58 4482.13,988.87 BATTERY.16@4482.13,513.9
BAT7: BATTERY.15 D33.2 D37.1 F8.1 R8.1 R114.1 | length 8819.2
  Top Layer w10: BATTERY.15@4619.92,513.9 4619.92,436.08 4856,200 5735,200 5795,260 5795,1037 5858,1100 6356.37,1100 6475,1218.63 6475,1336.09 6442,1369.09 6442,1568.75 6482,1608.75 6482,1737.28 6666.38,1921.65 R8.1@6717.29,1921.65
  Top Layer w90: F8.1@4428.42,1329 4428.42,1118.58 4604,943 4604,526.59 BATTERY.15@4616.69,513.9
  Bottom Layer w10: D37.1@4211.42,1393 4211.42,1452 4418.42,1659 5668.34,1659 5765.34,1756 5993.81,1756 6226.81,1989 6307.19,1989 6356.19,2038 6356.48,2038 6374.98,2056.5 6434.98,2056.5 6483.48,2105 6930.19,2105 R114.1@6931.41,2103.77
  Bottom Layer w20: D37.1@4211.42,1393 4247.42,1393 4270.42,1370 4270.42,1306 4283.81,1292.61 D33.2@4349.42,1292.61 4349.42,1261.58 4619.92,991.08 BATTERY.15@4619.92,513.9
BAT8: BATTERY.14 D30.2 D33.1 F7.2 R7.1 R112.1 | length 8483.2
  Top Layer w10: BATTERY.14@4759,513.9 4759,436 4977,218 5727.54,218 5777,267.46 5777,1044.46 5850.54,1118 6348.91,1118 6457,1226.09 6457,1328.63 6424,1361.63 6424,1576.21 6464,1616.21 6464,1744.73 6690.92,1971.65 R7.1@6716.85,1971.65
  Top Layer w90: F7.2@4570.42,1329 4570.42,1133.58 4717.92,986.08 4717.92,655.07 4757.72,615.27 BATTERY.14@4757.72,513.9
  Bottom Layer w10: D33.1@4349.42,1393 4349.42,1455 4535.42,1641 5675.8,1641 5772.8,1738 6001.27,1738 6234.27,1971 6314.65,1971 6363.65,2020 6363.94,2020 6382.44,2038.5 6442.44,2038.5 6490.94,2087 6814,2087 6847.23,2053.77 R112.1@6876.41,2053.77
  Bottom Layer w20: D33.1@4349.42,1393 4387.42,1393 4405.42,1375 4405.42,1310 4422.81,1292.61 D30.2@4458.42,1292.61 4458.42,1261.58 4757.72,962.28 BATTERY.14@4757.72,513.9
BAT9: BATTERY.5 D30.1 D41.2 F6.1 R6.1 R111.1 | length 7851.7
  Top Layer w10: BATTERY.5@4836.75,695 4836.75,613.25 4853,597 4922,597 4967.99,551.01 4967.99,387.53 5119.52,236 5720.09,236 5759,274.91 5759,1051.91 5843.09,1136 6341.46,1136 6439,1233.54 6439,1321.18 6406,1354.18 6406,1583.66 6446,1623.66 6446,1752.54 6713.11,2019.65 R6.1@6763.85,2019.65
  Top Layer w90: F6.1@4712.42,1327 4712.42,1152.58 4836.75,1028.25 BATTERY.5@4836.75,695
  Bottom Layer w10: D30.1@4458.42,1393 4458.42,1454 4627.42,1623 5683.25,1623 5780.25,1720 6008.72,1720 6241.72,1953 6607.87,1953 6618.22,1942.65 R111.1@6677.74,1942.65
  Bottom Layer w20: D30.1@4458.42,1393 4492.42,1393 4515.42,1370 4515.42,1309 4531.81,1292.61 D41.2@4566.42,1292.61 4566.42,1264.58 4836.46,994.54 BATTERY.5@4836.46,695
BAT10: BATTERY.4 D38.2 D41.1 F5.2 R5.1 R110.1 | length 7719.1
  Top Layer w10: BATTERY.4@4974.54,695 4974.54,586.46 4985.99,575.01 4985.99,400.64 5128.63,258 5502.46,258 5741,496.54 5741,1059.37 5835.63,1154 6334,1154 6420.75,1240.75 6420.75,1313.97 6388,1346.72 6388,1591.12 6428,1631.12 6428,1760 6779.21,2111.21 R5.1@6932.91,2111.21
  Top Layer w90: F5.2@4854.42,1329 4854.42,1171.58 4974.54,1051.46 BATTERY.4@4974.54,695
  Bottom Layer w10: D41.1@4566.42,1393 4566.42,1452 4719.42,1605 5690.71,1605 5787.71,1702 6016.18,1702 6249.18,1935 6600.42,1935 6646.76,1888.65 R110.1@6675.74,1888.65
  Bottom Layer w20: D41.1@4566.42,1393 4607.42,1393 4630.42,1370 4630.42,1319 4656.81,1292.61 D38.2@4703.42,1292.61 4703.42,1262.58 4974.25,991.75 BATTERY.4@4974.25,695
BAT11: BATTERY.3 D36.2 D38.1 F4.2 R4.1 R109.1 | length 7720.8
  Top Layer w10: BATTERY.3@5111,691 5111,631 5102,622 5051,622 5003.99,574.99 5003.99,408.1 5136.09,276 5495.01,276 5723,503.99 5723,1066.82 5828.18,1172 6326.14,1172 6400,1245.86 6400,1309.27 6370,1339.27 6370,1598.57 6410,1638.57 6410,1770.63 6789.37,2150 6969.42,2150 6986.91,2132.5 R4.1@6986.91,2111.21
  Top Layer w90: F4.2@4996.42,1329 4996.42,1188.58 5112.34,1072.66 BATTERY.3@5112.34,695
  Bottom Layer w10: D38.1@4703.42,1393 4703.42,1454 4836.42,1587 5698.16,1587 5795.16,1684 6023.63,1684 6256.63,1917 6567.42,1917 6650.76,1833.65 R109.1@6677.74,1833.65
  Bottom Layer w20: D38.1@4703.42,1393 4742.42,1393 4760.42,1375 4760.42,1319 4786.81,1292.61 D36.2@4840.42,1292.61 4840.42,1256.58 5112.05,984.95 BATTERY.3@5112.05,695
BAT12: BATTERY.2 D34.2 D36.1 F3.2 R3.1 R108.1 | length 7669.9
  Top Layer w10: BATTERY.2@5250.13,695 5250.13,628.13 5226,604 5058.46,604 5021.99,567.54 5021.99,415.55 5143.54,294 5487.55,294 5705,511.45 5705,1074.28 5820.72,1190 6234,1190 6290,1246 6290,1430 6350,1490 6350,1664.09 6391,1705.09 6391,1706 6392,1707 6392,1778.09 6781.91,2168 7006.42,2168 7042.91,2131.5 R3.1@7042.91,2111.21
  Top Layer w90: F3.2@5138.42,1329 5138.42,1207.58 5250.13,1095.87 BATTERY.2@5250.13,695
  Bottom Layer w10: D36.1@4840.42,1393 4840.42,1456 4953.42,1569 5705.62,1569 5802.62,1666 6031.09,1666 6264.09,1899 6525.42,1899 6646.76,1777.65 R108.1@6677.74,1777.65
  Bottom Layer w20: D36.1@4840.42,1393 4877.42,1393 4895.42,1375 4895.42,1326 4928.81,1292.61 D34.2@4979.42,1292.61 4979.42,1186.99 5249.84,916.56 BATTERY.2@5249.84,695
BAT13: BATTERY.10 D31.2 D34.1 F2.2 R2.1 R107.1 | length 8113.7
  Top Layer w10: BATTERY.10@5394.27,507.27 BATTERY.10@5387.64,513.9 5315.58,585.95 5233.5,585.95 5233.46,586 5065.91,586 5039.99,560.08 5039.99,423.01 5151,312 5480.1,312 5687,518.9 5687,1081.73 5813.27,1208 6171.76,1208 6191.42,1227.66 6191.42,1357.42 6287,1453 6287,1454.54 6331,1498.54 6331,1670.54 6373,1712.54 6373,1784.54 6774.46,2186 7044.42,2186 7096.91,2133.5 R2.1@7096.91,2111.21
  Top Layer w90: F2.2@5325.42,1281 5325.42,1180.58 5511,995 5511,624 BATTERY.10@5394.27,507.27
  Bottom Layer w10: D34.1@4979.42,1393 4979.42,1460 5070.42,1551 5713.08,1551 5810.08,1648 6038.54,1648 6271.54,1881 6491.42,1881 6648.76,1723.65 R107.1@6677.29,1723.65 R107.1@6671.95,1729
  Bottom Layer w20: D34.1@4979.42,1393 5037.42,1393 5080.42,1350 5080.42,1328 5115.81,1292.61 D31.2@5185.42,1292.61 5185.42,1055.58 5475,766 5475,601.26 BATTERY.10@5387.64,513.9
BAT14: BATTERY.9 BATTERY.11 D42.2 F1.2 Q25.2 Q48.2 R89.2 R129.1 R183.2 | length 4372.2
  Top Layer w30: F1.2@5467.42,1281 5468.42,1281 v3@5575,1281 ; v3(5575,1232) v3@5575,1281 ; v3@5575,1281 5576,1281 v3(5575,1282) v3@5575,1281
  Top Layer w50: F1.2@5467.42,1280 F1.2@5468.42,1281
  Top Layer w100: BATTERY.11@5249.84,513.9 5249.84,425.16 5294,381 5460,381 5624,545 5624,1050 5467.42,1206.58 F1.2@5467.42,1280
  MidLayer2 w100: BATTERY.9@3852.2,695 3775,695 3709,629 3709,450 3777,382 5192,382 5249.84,439.84 BATTERY.11@5249.84,513.9
  Bottom Layer w20: v3(5575,1232) 5628,1232 ; Q25.2@5649.2,1165 5649.2,1210.8 5628,1232 ; Q48.2@5877,1378.8 5838.8,1378.8 5829,1369 R183.2@5814,1369 R89.2@5766,1369 5740,1369 5728,1381 5686,1381 5672,1367 5672,1324 5628,1280 5628,1232
  Bottom Layer w30: R129.1@5294.42,1313 D42.2@5404.42,1313 5500,1313 5531,1282 v3(5575,1282) v3(5575,1232)
BAT14S_: D31.1 Q40.2 R1.1 R106.1 R126.2 R129.2 | length 5963
  Top Layer w10: v3(5576,1325) 5601,1325 5700,1226 6164.3,1226 6173.42,1235.12 6173.42,1366.42 6313,1506 6313,1678 6355,1720 6355,1792 6767,2204 7053.42,2204 7083.42,2173.99 7126.42,2173.99 7126.42,2154.58 7152.91,2128.09 R1.1@7152.91,2111.21
  Top Layer w20: v3@6769,1084 6768.42,1084 6838.82,1154.4 Q40.2@6838.82,1181.32 ; R1.1@7152.91,2111.21 R1.1@7153.13,2111
  MidLayer3 w20: v3(5576,1325) 5581.5,1325 5610,1296.5 5610,1191 5731,1070 5865.5,1070 5895.5,1040 6361.5,1040 6382.5,1019 6639.92,1019 6704.92,1084 v3(6764.42,1084) ; v3@6766,1081 v3@6769,1084
  Bottom Layer w10: R129.2@5294.42,1393 5294.42,1478 5349.42,1533 5720.53,1533 5817.53,1630 6046,1630 6279,1863 6465.42,1863 6655.42,1673 R106.1@6677.42,1673
  Bottom Layer w20: D31.1@5185.42,1393 R129.2@5294.42,1393 5508,1393 v3(5576,1325)
C0: C189.2 C192.1 D55.2 D56.2 R130.2 U18.22 | length 1611.2
  MidLayer1 w20: v3(6537,1430) 6560.52,1430 6627.81,1497.29 6694.1,1497.29 7162.81,1966 7339,1966 v3(7360,1945)
  Bottom Layer w10: U18.22@7209.59,1769.78 7209.59,1785.21 7222.38,1798 7292.82,1798 7359.42,1864.6 7359.42,1964.42 7364.41,1969.41 C192.1@7364.41,1998.65 C189.2@7316.53,1998.65 R130.2@7316.53,2048.54
  Bottom Layer w20: v3(6537,1430) 6541.42,1430 6541.42,1417.42 6535,1411 6535,1379.53 D56.2@6535.42,1379.12 6536.3,1380 D55.2@6602.42,1380
C1: C186.2 C189.1 R124.2 U18.21 | length 308.6
  Bottom Layer w10: U18.21@7189.91,1769.78 7189.91,1794.14 7226.42,1830.65 7226.42,1860 7246.42,1880 7246.42,1893.08 7261.53,1908.2 C186.2@7261.53,1950.65 7261.53,1998.54 C189.1@7261.41,1998.65 R124.2@7261.41,2048.65
C2: C184.2 C186.1 R123.2 U18.20 | length 302.2
  Bottom Layer w10: U18.20@7170.22,1769.78 7170.22,1816.89 7208.42,1855.08 7208.42,1868 7216.42,1876 7216.42,1919 7206.41,1929 C186.1@7206.41,1950.65 C184.2@7206.53,1998.65 7206.53,2048.54 R123.2@7206.41,2048.65
C3: C108.2 C184.1 R122.2 U18.19 | length 290.6
  Bottom Layer w10: U18.19@7150.54,1769.78 7150.54,1837.58 7163.42,1850.46 7163.42,1921 7151.53,1932.89 C108.2@7151.53,1950.65 ; C108.2@7150.54,1949.66 C108.2@7151.53,1950.65 ; R122.2@7151.41,2048.65 C184.1@7151.41,1998.65 7151.53,1998.54 C108.2@7151.53,1950.65
C4: C108.1 C193.2 R120.2 U18.18 | length 293.2
  Bottom Layer w10: R120.2@7096.41,2048.65 7096.53,2048.54 C193.2@7096.53,1998.65 7096.53,1950.77 C108.1@7096.41,1950.65 7096.41,1914.66 7130.85,1880.22 U18.18@7130.85,1769.78
C5: C190.2 C193.1 R118.2 U18.17 | length 314.8
  Bottom Layer w10: R118.2@7040.41,2048.65 7041.41,2047.65 C193.1@7041.41,1998.65 7041.53,1998.54 C190.2@7041.53,1950.65 7041.53,1916.54 7087.42,1870.65 7098.76,1870.65 7111.17,1858.25 U18.17@7111.17,1769.78
C6: C187.2 C190.1 R116.2 U18.16 | length 328.6
  Bottom Layer w10: R116.2@6986.41,2048.65 6986.53,2048.54 C187.2@6986.53,1998.65 6986.41,1998.54 C190.1@6986.41,1950.65 6986.41,1921 6991.42,1916 7001.84,1916 7026.42,1891.43 7026.42,1889 7091.48,1823.94 U18.16@7091.48,1769.78
C7: C183.2 C187.1 R114.2 U18.15 | length 345.2
  Bottom Layer w10: R114.2@6931.41,2048.65 C187.1@6931.41,1998.65 6931.53,1998.54 C183.2@6931.53,1950.65 6931.53,1929.89 6948.42,1913 6956.42,1913 6990.42,1879 6996.42,1879 6996.42,1874 7071.8,1798.62 U18.15@7071.8,1769.78
C8: C109.2 C183.1 R112.2 U18.14 | length 375.4
  Bottom Layer w10: C109.2@6827.98,1999 6828.32,1998.65 R112.2@6876.41,1998.65 C183.1@6876.41,1950.65 6876.41,1925.65 6900.07,1902 6930.3,1902 6983.3,1849 6995.96,1849 7052.11,1792.85 U18.14@7052.11,1769.78
C9: C109.1 C194.2 R111.2 U18.13 | length 440.6
  Bottom Layer w10: R111.2@6732.85,1942.65 6733.85,1943.65 C194.2@6780.41,1943.65 ; C109.1@6772.86,1999 6772.86,1977.56 6780.41,1970 C194.2@6780.41,1943.65 ; U18.13@7032.43,1769.78 7032.43,1786.99 6991.42,1828 6978.84,1828 6922.84,1884 6883.93,1884 6824.4,1943.54 6780.53,1943.54 C194.2@6780.41,1943.65
C10: C191.2 C194.1 R110.2 U18.12 | length 343.8
  Bottom Layer w10: R110.2@6730.85,1888.65 6730.97,1888.54 C194.1@6780.41,1888.54 6780.53,1888.65 C191.2@6828.41,1888.65 6848.76,1888.65 6896.76,1840.65 6923.76,1840.65 7006.84,1757.58 U18.12@7006.84,1744.19
C11: C188.2 C191.1 R109.2 U18.11 | length 319.2
  Bottom Layer w10: R109.2@6732.85,1833.65 C188.2@6780.41,1833.65 6828.29,1833.65 C191.1@6828.41,1833.54 6854.88,1833.54 6882.42,1806 6902.42,1806 6983.91,1724.51 U18.11@7006.84,1724.51
C12: C185.2 C188.1 R108.2 U18.10 | length 305
  Bottom Layer w10: R108.2@6732.85,1777.65 6733.74,1778.54 C188.1@6780.41,1778.54 6780.53,1778.65 C185.2@6828.41,1778.65 6852.76,1778.65 6882.42,1749 6925.5,1749 6969.68,1704.82 U18.10@7006.84,1704.82
C13: C110.2 C185.1 R107.2 U18.9 | length 290.4
  Bottom Layer w10: R107.2@6732.41,1723.65 C110.2@6780.41,1723.65 6828.29,1723.65 C185.1@6828.41,1723.54 6853.88,1723.54 6882.42,1695 6954.05,1695 6963.91,1685.14 U18.9@7006.84,1685.14
C14: C110.1 D53.2 D54.2 R106.2 U18.8 | length 776.4
  Bottom Layer w10: D54.2@6404,1837.56 6457.35,1837.56 6655.99,1638.92 6698.43,1638.92 6698.5,1639 6725.42,1639 6732.41,1646 R106.2@6732.41,1668.65 6732.53,1668.54 C110.1@6780.41,1668.54 6830.95,1668.54 6834.49,1665 7006.38,1665 U18.8@7006.84,1665.45
  Bottom Layer w20: D53.2@6340,1837.56 D54.2@6404,1837.56
CAN_GND: C13.1 C14.1 C57.1 C59.2 C81.1 C100.1 CAN_POWER.1 CAN_POWER.3 L1.1 P3.A3 P3.A7 P3.B3 P3.B7 R62.2 R66.2 R164.1 R252.2 U4.1 U5.2 | length 1668.3
  Top Layer w20: R164.1@487.88,1945 487.88,1915.12 502.56,1900.44 v3(537.88,1900.44) v3(537.88,1860.44) ; v6@595,1344.88 v6(597,1342.88) ; v6(597,1302.88) v6(597,1342.88) ; R252.2@597,1442.88 v6(597,1342.88)
  Bottom Layer w20: v3(537.88,1860.44) v3(537.88,1900.44) R62.2@537.88,1945 ; P3.A7@588,682 588,607 642,553 C100.1@738,553 787,553 797.01,542.99 L1.1@827,542.99 877.99,542.99 938,603 P3.B3@938,682 ; v6(597,1302.88) v6(597,1342.88) R66.2@597,1387.44 ; v6(602,879) v6(602,929) C59.2@602,972.88 ; v6(710.44,1833.56) v6(710.44,1793.56) C81.1@710.44,1749 710.44,1634.05 U5.2@713,1631.49 ; v6(881,884) v6(881,934) C57.1@881,977.88 ; U4.1@913,2037.96 913,2007 930.56,1989.44 C13.1@930.56,1971 955,1971 981.3,1944.7 C14.1@981.3,1901 v6(981.3,1836.44) v6(981.3,1796.44)
D0: C181.2 C182.1 R15.2 U2.22 | length 429.6
  Top Layer w10: R15.2@6724.47,1480.65 6724.91,1481.1 C181.2@6771.91,1481.1 C181.2@6771.91,1471.1 ; C181.2@6771.47,1470.65 C181.2@6771.91,1471.1 ; U2.22@7006.84,1567.03 6991.4,1567.03 6951.42,1527.04 6951.42,1490.06 6959.92,1481.56 6959.92,1460.44 6941.51,1442.03 6817.02,1442.03 6807.99,1433 C182.1@6785.98,1433 6785.98,1453.44 6771.91,1467.5 C181.2@6771.91,1471.1
D1: C180.2 C181.1 R14.2 U2.21 | length 312.9
  Top Layer w10: R14.2@6724.47,1525.65 R14.2@6725.03,1526.21 ; R14.2@6724.47,1535.65 6725.03,1536.21 C181.1@6771.91,1536.21 6772.03,1536.1 C180.2@6819.91,1536.1 6845.32,1536.1 6855.32,1526.1 6920.51,1526.1 6981.13,1586.71 U2.21@7006.84,1586.71 ; C181.1@6771.91,1526.21 C181.1@6772.03,1526.1
D2: C179.2 C180.1 R13.2 U2.20 | length 297.6
  Top Layer w10: R13.2@6724.47,1580.65 R13.2@6724.91,1581.1 ; R13.2@6724.47,1591.21 C179.2@6771.91,1591.21 ; C179.2@6771.91,1581.1 C179.2@6772.03,1581.21 ; C179.2@6772.03,1591.1 C180.1@6819.91,1591.1 ; C180.1@6819.91,1591.21 6842.2,1591.21 6852.2,1581.21 6898.63,1581.21 6923.81,1606.4 U2.20@7006.84,1606.4
D3: C178.2 C179.1 R12.2 U2.19 | length 291.5
  Top Layer w10: R12.2@6724.47,1646.21 C179.1@6771.91,1646.21 ; C179.1@6771.35,1635.65 C179.1@6771.91,1636.21 ; C179.1@6772.03,1646.1 C178.2@6819.91,1646.1 6851.32,1646.1 6861.32,1636.1 6897.32,1636.1 6907.33,1626.08 U2.19@7006.84,1626.08 ; C178.2@6819.79,1636.21 C178.2@6819.91,1636.1
D4: C177.2 C178.1 R11.2 U2.18 | length 306
  Top Layer w10: R11.2@6724.47,1701.21 C177.2@6771.91,1701.21 ; C177.2@6771.47,1690.65 C177.2@6771.91,1691.1 ; C177.2@6772.03,1701.1 C178.1@6819.91,1701.1 ; C178.1@6819.79,1691.1 C178.1@6819.91,1691.21 ; C178.1@6819.91,1701.21 6860.42,1701.21 6870.42,1691.21 6908.12,1691.21 6953.57,1645.77 U2.18@7006.84,1645.77
D5: C176.2 C177.1 R10.2 U2.17 | length 333.2
  Top Layer w10: R10.2@6724.47,1756.21 C177.1@6771.91,1756.21 ; C177.1@6771.35,1745.65 C177.1@6771.91,1746.21 ; C177.1@6772.03,1756.1 C176.2@6819.91,1756.1 6845.32,1756.1 6855.32,1746.1 6868.53,1746.1 ; 6868.42,1746.21 6868.53,1746.1 ; U2.17@7006.84,1665.45 7006.63,1665.65 6959.13,1665.65 6910.42,1714.37 6910.42,1735.6 6899.92,1746.1 6868.53,1746.1
D6: C175.2 C176.1 R9.2 U2.16 | length 350.2
  Top Layer w10: R9.2@6724.47,1811.21 C175.2@6771.91,1811.21 ; C175.2@6771.47,1800.65 C175.2@6771.91,1801.1 ; C175.2@6772.03,1811.1 C176.1@6819.91,1811.1 ; C176.1@6819.91,1811.21 6864.79,1811.21 6928.42,1747.58 6928.42,1721.83 6965.11,1685.14 U2.16@7006.84,1685.14
D7: C174.2 C175.1 R8.2 U2.15 | length 385.3
  Top Layer w10: C175.1@6771.35,1855.65 C175.1@6771.91,1856.21 ; R8.2@6771.91,1911.15 R8.2@6772.41,1911.65 ; R8.2@6772.41,1921.65 R8.2@6772.41,1911.65 ; C174.2@6819.79,1856.21 6829.79,1866.21 6847.2,1866.21 6946.42,1767 6946.42,1729.28 6970.88,1704.82 U2.15@7006.84,1704.82 ; C174.2@6819.91,1866.1 6819.79,1866.21 C175.1@6771.91,1866.21 6772.41,1866.71 R8.2@6772.41,1911.65
D8: C173.2 C174.1 R7.2 U2.14 | length 397.7
  Top Layer w10: R7.2@6771.97,1971.65 C173.2@6819.35,1971.65 ; C174.1@6819.91,1915.21 6842.2,1915.21 6964.42,1793 6964.42,1736.74 6976.65,1724.51 U2.14@7006.84,1724.51 ; C174.1@6819.91,1921.21 6819.35,1921.77 C173.2@6819.35,1971.65 ; C173.2@6819.91,1971.1 C173.2@6819.35,1971.65
D9: C172.2 C173.1 R6.2 U2.13 | length 381.6
  Top Layer w10: R6.2@6818.97,2019.65 6842.35,2019.65 6852.35,2009.65 C172.2@6877.35,2009.65 6877.47,2009.54 C173.1@6877.47,1961.65 6877.47,1922.94 7006.84,1793.58 U2.13@7006.84,1744.19
D10: C171.2 C172.1 R5.2 U2.12 | length 329.3
  Top Layer w10: C172.1@6932.35,2009.65 C171.2@6932.35,1961.65 6932.35,1914.06 7032.43,1813.99 U2.12@7032.43,1769.78 ; C172.1@6932.47,2009.65 R5.2@6932.47,2057.65
D11: C152.2 C171.1 R4.2 U2.11 | length 314.6
  Top Layer w10: C152.2@6987.35,2009.65 R4.2@6987.35,2057.65 ; C152.2@6987.47,2009.65 C171.1@6987.47,1961.65 6987.47,1884.4 7052.11,1819.76 U2.11@7052.11,1769.78
D12: C26.2 C152.1 R3.2 U2.10 | length 300.1
  Top Layer w10: R3.2@7042.35,2057.65 7042.35,2009.65 C26.2@7042.35,1961.65 7042.35,1879.06 7071.8,1849.62 U2.10@7071.8,1769.78
D13: C23.2 C26.1 R2.2 U2.9 | length 290.4
  Top Layer w10: U2.9@7091.48,1769.78 7091.48,1865.06 7097.47,1871.06 C26.1@7097.47,1961.65 R2.2@7097.47,2057.65
D14: C23.1 R1.2 U2.8 | length 303.6
  Top Layer w10: U2.8@7111.17,1769.78 7111.17,1856.75 7146.42,1892 7146.42,1979 7152.42,1985 7152.42,2009.6 C23.1@7152.47,2009.65 7152.47,2055.66 R1.2@7152.91,2056.1
DIN_LS: D54.1 Q25.3 Q54.3 R182.1 | length 1189.2
  MidLayer2 w20: v3(5715,1344) 5715,1609 5778,1672 v6(6247,1672)
  Bottom Layer w20: Q25.3@5686.6,1243.74 Q25.3@5686.6,1247.68 5686.6,1287.6 5715,1316 v3(5715,1344) ; v6(6247,1672) 6296.4,1672 Q54.3@6296.6,1671.8 6325.8,1671.8 6349,1695 R182.1@6403.86,1695 6404,1695.14 D54.1@6404,1782.44
DIR_BOT: U6.25 U27.9 | length 1866
  Top Layer w10: U27.9@4721.62,3728.92 4809.33,3728.92 v5(4921.42,3841) ; U6.25@5152.77,2767.98 5265.3,2768 5283.3,2750 5335.42,2750 v5(5365.42,2720)
  MidLayer2 w10: v5(4921.42,3841) 5042,3720.42 5042,3259.78 5149.42,3152.37 5149.42,2996.21 5179.42,2966.21 5179.42,2838.5 5206.91,2811 5347.42,2811 5365.42,2793 v5(5365.42,2720)
DIR_RT_BOT: U6.24 U27.10 | length 1935.4
  Top Layer w10: U27.10@4721.62,3754.51 4778.29,3754.51 4921.42,3897.63 v5(4921.42,3941) ; U6.24@5127.18,2742.39 5163.8,2742.39 5171.42,2750 5257.84,2750 5287.84,2720 v4(5305.42,2720)
  MidLayer2 w10: v5(4921.42,3941) 4921.42,3883.43 4891.42,3853.43 4891.42,3773.58 5006,3659 5006,3244.87 5113.42,3137.46 5113.42,2981.3 5143.42,2951.3 5143.42,2823.58 5217,2750 5275.42,2750 v4(5305.42,2720)
DIR_RT_TOP: U26.24 U29.10 | length 2309.8
  Top Layer w10: U26.24@6796.18,2302.14 6796.33,2302 7101.28,2302 7122.28,2323 7210.18,2323 7246.42,2359.24 7246.42,2903.35 7180.42,2969.35 7180.42,3218.54 7265.42,3303.54 7265.42,3636.92 7141.68,3760.66 U29.10@6821.05,3760.66
DIR_TOP: U26.25 U29.9 | length 2224.6
  Top Layer w10: U29.9@6821.05,3735.06 7141.82,3735.06 7247.42,3629.47 7247.42,3360 7162.42,3275 7162.42,2961.9 7228.42,2895.9 7228.42,2366.7 7202.72,2341 7114.82,2341 7093.82,2320 6918.05,2320 6910.32,2327.73 U26.25@6821.77,2327.73
DONE_BOT: U6.23 U27.11 | length 1756.8
  Top Layer w10: U27.11@4721.62,3780.1 4778.43,3780.1 4871.42,3873.09 v5(4871.42,3941) ; U6.23@5107.5,2742.39 5107.5,2726.95 5132.45,2702 5173.42,2702 v4@5191.42,2720
  MidLayer2 w10: v5(4871.42,3941) 4871.42,3680.54 4885.42,3666.54 4885.42,3486.57 4962.42,3409.57 4962.42,3263 5044.5,3180.92 5044.5,3109.08 5031.42,3096 5031.42,3037.84 5125.42,2943.84 5125.42,2753.46 5158.87,2720 v4(5185.42,2720) v4@5191.42,2720
DONE_TOP: U26.23 U29.11 | length 2415.4
  Top Layer w10: U26.23@6776.5,2302.14 6776.5,2286.71 6787.21,2276 7074.15,2276 7082.15,2284 7108.73,2284 7129.73,2305 7217.63,2305 7264.42,2351.78 7264.42,2910.81 7198.42,2976.81 7198.42,3211.09 7283.42,3296.09 7283.42,3644.38 7141.55,3786.25 U29.11@6821.05,3786.25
